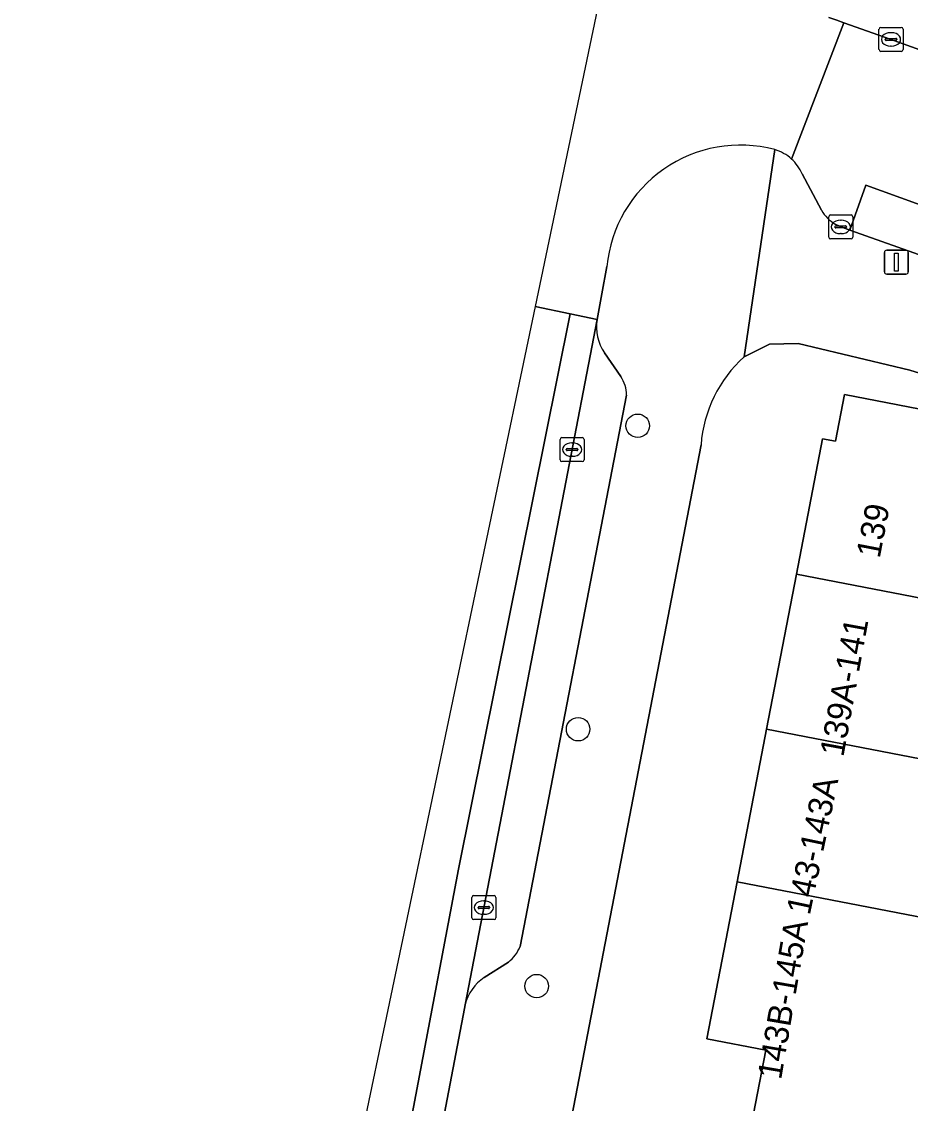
# Model space of a CAD drawing. Extents: x 159817 to 160765, y 380688 to 381638.
# Drawn here: x 159990.41 to 160027.41, y 381065.22 to 381110.28 of the extents above; entities that cross this region are included whole.
import ezdxf

# ---------------------------------------------------------------- set-up
doc = ezdxf.new("R2010")
doc.units = 0
for name, color, linetype in [('IMGEO_Boom', 7, 'Continuous'), ('IMGEO_Erf', 7, 'Continuous'), ('IMGEO_Kolk', 7, 'Continuous'), ('IMGEO_Lichtmast', 7, 'Continuous'), ('IMGEO_Pand', 7, 'Continuous'), ('IMGEO_Pand_nummerreeks', 7, 'Continuous'), ('IMGEO_Parkeervlak_open', 7, 'Continuous'), ('IMGEO_Rijbaan_lokaal_gesloten', 7, 'Continuous'), ('IMGEO_Rijbaan_lokaal_open', 7, 'Continuous'), ('IMGEO_Voetpad_open', 7, 'Continuous')]:
    doc.layers.add(name, color=color, linetype=linetype)

msp = doc.modelspace()

# ---------------------------------------------------------------- linework, layer by layer
at = {"layer": 'IMGEO_Boom'}
for centre in [(160016.059, 381093.448), (160013.577, 381080.809), (160011.851, 381070.108)]:
    msp.add_circle(centre, 0.489, dxfattribs=at)
at = {"layer": 'IMGEO_Erf'}
for points in [[(160050.272, 381088.672), (160027.383, 381095.765), (160022.739, 381096.87), (160021.552, 381096.842), (160020.487, 381096.319)], [(160018.697, 381092.654), (160013.182, 381063.968), (160020.449, 381062.565), (160021.389, 381067.434), (160018.934, 381067.908), (160020.197, 381074.451), (160021.425, 381080.816), (160022.671, 381087.27), (160023.759, 381092.908), (160024.29, 381092.806), (160024.664, 381094.748), (160029.108, 381093.89), (160028.732, 381091.944), (160032.76, 381091.167), (160032.532, 381089.988), (160036.377, 381088.829), (160049.13, 381084.986), (160050.272, 381088.672)]]:
    msp.add_lwpolyline(points, dxfattribs=at)
msp.add_arc((160024.132, 381092.269), 5.449, 131.9899, 175.9479, dxfattribs=at)
at = {"layer": 'IMGEO_Kolk'}
for p, q in [((160026.105, 381109.115), (160026.105, 381109.967)), ((160026.18, 381110.041), (160027.032, 381110.041)), ((160026.593, 381109.821), (160026.618, 381109.821)), ((160027.106, 381109.967), (160027.106, 381109.115)), ((160026.364, 381109.535), (160026.364, 381109.547)), ((160026.802, 381109.498), (160026.404, 381109.498)), ((160026.407, 381109.584), (160026.805, 381109.584)), ((160026.848, 381109.547), (160026.848, 381109.535)), ((160027.032, 381109.041), (160026.18, 381109.041)), ((160026.616, 381109.261), (160026.591, 381109.261)), ((160024.013, 381101.304), (160024.013, 381102.156)), ((160024.088, 381102.23), (160024.94, 381102.23)), ((160025.014, 381102.156), (160025.014, 381101.304)), ((160024.272, 381101.724), (160024.272, 381101.736)), ((160024.315, 381101.773), (160024.713, 381101.773)), ((160024.501, 381102.01), (160024.526, 381102.01)), ((160024.756, 381101.736), (160024.756, 381101.724)), ((160024.71, 381101.687), (160024.312, 381101.687)), ((160024.524, 381101.45), (160024.499, 381101.45)), ((160024.94, 381101.23), (160024.088, 381101.23)), ((160012.826, 381092.029), (160012.826, 381092.881)), ((160012.901, 381092.955), (160013.753, 381092.955)), ((160013.314, 381092.735), (160013.339, 381092.735)), ((160013.827, 381092.881), (160013.827, 381092.029)), ((160013.085, 381092.449), (160013.085, 381092.461)), ((160013.523, 381092.412), (160013.125, 381092.412)), ((160013.128, 381092.498), (160013.526, 381092.498)), ((160013.569, 381092.461), (160013.569, 381092.449)), ((160013.753, 381091.955), (160012.901, 381091.955)), ((160013.337, 381092.175), (160013.312, 381092.175)), ((160009.152, 381072.954), (160009.152, 381073.806)), ((160009.227, 381073.88), (160010.079, 381073.88)), ((160010.153, 381073.806), (160010.153, 381072.954)), ((160009.411, 381073.374), (160009.411, 381073.386)), ((160009.849, 381073.337), (160009.451, 381073.337)), ((160009.454, 381073.423), (160009.852, 381073.423)), ((160009.64, 381073.66), (160009.665, 381073.66)), ((160009.895, 381073.386), (160009.895, 381073.374)), ((160010.079, 381072.88), (160009.227, 381072.88)), ((160009.663, 381073.1), (160009.638, 381073.1))]:
    msp.add_line(p, q, dxfattribs=at)
for points in [[(160026.105, 381109.115), (160026.105, 381109.967)], [(160026.18, 381110.041), (160027.032, 381110.041)], [(160027.106, 381109.967), (160027.106, 381109.115)], [(160027.032, 381109.041), (160026.18, 381109.041)], [(160024.013, 381101.304), (160024.013, 381102.156)], [(160024.088, 381102.23), (160024.94, 381102.23)], [(160025.014, 381102.156), (160025.014, 381101.304)], [(160024.94, 381101.23), (160024.088, 381101.23)], [(160012.826, 381092.029), (160012.826, 381092.881)], [(160012.901, 381092.955), (160013.753, 381092.955)], [(160013.827, 381092.881), (160013.827, 381092.029)], [(160013.753, 381091.955), (160012.901, 381091.955)], [(160009.152, 381072.954), (160009.152, 381073.806)], [(160009.227, 381073.88), (160010.079, 381073.88)], [(160010.153, 381073.806), (160010.153, 381072.954)], [(160010.079, 381072.88), (160009.227, 381072.88)]]:
    msp.add_lwpolyline(points, dxfattribs=at)
for centre, radius, start, end in [((160026.182, 381109.965), 0.0765, 91.552, 178.448), ((160026.182, 381109.965), 0.0765, 91.552, 178.448), ((160027.03, 381109.965), 0.0765, 1.552, 88.448), ((160027.03, 381109.965), 0.0765, 1.552, 88.448), ((160026.404, 381109.544), 0.0403, 85.8775, 175.7526), ((160026.401, 381109.534), 0.0366, 178.938, 274.7102), ((160026.805, 381109.541), 0.043, 264.8664, 352.4533), ((160026.809, 381109.546), 0.0386, 1.7309, 96.639), ((160026.182, 381109.117), 0.0765, 181.552, 268.448), ((160026.182, 381109.117), 0.0765, 181.552, 268.448), ((160027.03, 381109.117), 0.0765, 271.552, 358.448), ((160027.03, 381109.117), 0.0765, 271.552, 358.448), ((160024.09, 381102.154), 0.0765, 91.552, 178.448), ((160024.09, 381102.154), 0.0765, 91.552, 178.448), ((160024.938, 381102.154), 0.0765, 1.552, 88.448), ((160024.938, 381102.154), 0.0765, 1.552, 88.448), ((160024.312, 381101.733), 0.0403, 85.8775, 175.7526), ((160024.309, 381101.723), 0.0366, 178.938, 274.7102), ((160024.713, 381101.73), 0.043, 264.8664, 352.4533), ((160024.717, 381101.735), 0.0386, 1.7309, 96.639), ((160024.09, 381101.306), 0.0765, 181.552, 268.448), ((160024.09, 381101.306), 0.0765, 181.552, 268.448), ((160024.938, 381101.306), 0.0765, 271.552, 358.448), ((160024.938, 381101.306), 0.0765, 271.552, 358.448), ((160012.903, 381092.879), 0.0765, 91.552, 178.448), ((160012.903, 381092.879), 0.0765, 91.552, 178.448), ((160013.751, 381092.879), 0.0765, 1.552, 88.448), ((160013.751, 381092.879), 0.0765, 1.552, 88.448), ((160013.125, 381092.458), 0.0403, 85.8775, 175.7526), ((160013.122, 381092.448), 0.0366, 178.938, 274.7102), ((160013.526, 381092.455), 0.043, 264.8664, 352.4533), ((160013.53, 381092.46), 0.0386, 1.7309, 96.639), ((160012.903, 381092.031), 0.0765, 181.552, 268.448), ((160012.903, 381092.031), 0.0765, 181.552, 268.448), ((160013.751, 381092.031), 0.0765, 271.552, 358.448), ((160013.751, 381092.031), 0.0765, 271.552, 358.448), ((160009.229, 381073.804), 0.0765, 91.552, 178.448), ((160009.229, 381073.804), 0.0765, 91.552, 178.448), ((160010.077, 381073.804), 0.0765, 1.552, 88.448), ((160010.077, 381073.804), 0.0765, 1.552, 88.448), ((160009.451, 381073.383), 0.0403, 85.8775, 175.7526), ((160009.448, 381073.373), 0.0366, 178.938, 274.7102), ((160009.852, 381073.38), 0.043, 264.8664, 352.4533), ((160009.856, 381073.385), 0.0386, 1.7309, 96.639), ((160009.229, 381072.956), 0.0765, 181.552, 268.448), ((160009.229, 381072.956), 0.0765, 181.552, 268.448), ((160010.077, 381072.956), 0.0765, 271.552, 358.448), ((160010.077, 381072.956), 0.0765, 271.552, 358.448)]:
    msp.add_arc(centre, radius, start, end, dxfattribs=at)
for centre, major_axis, ratio, start_param, end_param in [((160026.592, 381109.541), (-0.387, 0.002), 0.722429, 4.712389, 7.853982), ((160026.617, 381109.541), (-0.39, 0.002), 0.717154, 1.570796, 4.712389), ((160024.5, 381101.73), (-0.387, 0.002), 0.722429, 4.712389, 7.853982), ((160024.525, 381101.73), (-0.39, 0.002), 0.717154, 1.570796, 4.712389), ((160013.313, 381092.455), (-0.387, 0.002), 0.722429, 4.712389, 7.853982), ((160013.338, 381092.455), (-0.39, 0.002), 0.717154, 1.570796, 4.712389), ((160009.639, 381073.38), (-0.387, 0.002), 0.722429, 4.712389, 7.853982), ((160009.664, 381073.38), (-0.39, 0.002), 0.717154, 1.570796, 4.712389)]:
    msp.add_ellipse(centre, major_axis=major_axis, ratio=ratio, start_param=start_param, end_param=end_param, dxfattribs=at)
at = {"layer": 'IMGEO_Lichtmast'}
for p, q in [((160026.333, 381099.862), (160026.333, 381100.662)), ((160026.333, 381100.662), (160026.333, 381099.862)), ((160026.433, 381100.762), (160027.223, 381100.762)), ((160027.223, 381100.762), (160026.433, 381100.762)), ((160027.323, 381100.662), (160027.323, 381099.862)), ((160027.323, 381099.862), (160027.323, 381100.662)), ((160027.223, 381099.762), (160026.433, 381099.762)), ((160026.433, 381099.762), (160027.223, 381099.762))]:
    msp.add_line(p, q, dxfattribs=at)
msp.add_lwpolyline([(160026.753, 381100.637), (160026.903, 381100.637), (160026.903, 381099.887), (160026.753, 381099.887), (160026.753, 381100.637)], dxfattribs=at)
for centre, start, end in [((160026.433, 381100.662), 90, 180), ((160026.433, 381100.662), 90, 180), ((160027.223, 381100.662), 0, 90), ((160027.223, 381100.662), 360, 90), ((160026.433, 381099.862), 180, 270), ((160026.433, 381099.862), 180, 270), ((160027.223, 381099.862), 270, 0), ((160027.223, 381099.862), 270, 0)]:
    msp.add_arc(centre, 0.1, start, end, dxfattribs=at)
at = {"layer": 'IMGEO_Pand'}
for points in [[(160035.179, 381084.856), (160036.377, 381088.829), (160032.532, 381089.988), (160032.76, 381091.167), (160028.732, 381091.944), (160029.108, 381093.89), (160024.664, 381094.748), (160024.29, 381092.806), (160023.759, 381092.908), (160022.671, 381087.27)], [(160021.425, 381080.816), (160034.222, 381078.346), (160034.983, 381082.289), (160034.453, 381082.449), (160035.179, 381084.856), (160022.671, 381087.27)], [(160021.425, 381080.816), (160020.197, 381074.451), (160038.181, 381070.98), (160039.211, 381077.288), (160034.222, 381078.346)], [(160038.181, 381070.98), (160020.197, 381074.451), (160018.934, 381067.908), (160021.389, 381067.434), (160020.449, 381062.565), (160025.359, 381061.617), (160037.632, 381059.249), (160037.702, 381059.613), (160038.584, 381064.177), (160038.637, 381064.454), (160037.162, 381064.74)]]:
    msp.add_lwpolyline(points, close=True, dxfattribs=at)
at = {"layer": 'IMGEO_Parkeervlak_open'}
msp.add_lwpolyline([(160024.886, 381101.599), (160029.549, 381099.944), (160043.748, 381094.789), (160047.251, 381093.529), (160047.916, 381095.371), (160025.551, 381103.473)], close=True, dxfattribs=at)
for points in [[(160014.37, 381097.873), (160008.872, 381069.326)], [(160015.36, 381095.497), (160014.672, 381096.487)], [(160011.162, 381071.761), (160015.595, 381094.725)], [(160009.67, 381070.467), (160010.674, 381071.111)]]:
    msp.add_lwpolyline(points, dxfattribs=at)
for centre, radius, start, end in [((160016.26, 381097.559), 1.916, 170.5634, 214.021), ((160014.141, 381094.704), 1.454, 0.8241, 33.0369), ((160009.739, 381072.321), 1.529, 307.6874, 338.5165), ((160010.708, 381068.892), 1.886, 123.3741, 166.6891)]:
    msp.add_arc(centre, radius, start, end, dxfattribs=at)
at = {"layer": 'IMGEO_Rijbaan_lokaal_gesloten'}
for points in [[(159996.492, 381024.81), (159998.992, 381024.304), (160001.883, 381039.437), (160008.595, 381074.982), (160013.251, 381098.111), (160011.786, 381098.422), (159998.48, 381034.852)], [(160007.891, 381064.168), (160008.842, 381069.172), (160008.872, 381069.326), (160014.37, 381097.873), (160013.251, 381098.111), (160008.595, 381074.982), (160001.883, 381039.437), (159998.992, 381024.304), (160000.051, 381024.089), (160000.137, 381024.388)]]:
    msp.add_lwpolyline(points, close=True, dxfattribs=at)
at = {"layer": 'IMGEO_Rijbaan_lokaal_open'}
for points in [[(160019.877, 381118.182), (160020.066, 381119.039), (160019.037, 381119.34), (160017.102, 381119.905), (160017.102, 381119.905), (160015.579, 381116.542), (160011.786, 381098.422)], [(160022.465, 381104.557), (160024.642, 381110.234), (160024.343, 381110.34), (160024.015, 381110.456)], [(160046.79, 381102.26), (160038.233, 381105.355), (160026.573, 381109.552), (160024.642, 381110.234), (160022.465, 381104.557)], [(160022.905, 381103.939), (160023.713, 381102.422)], [(160024.277, 381101.844), (160024.486, 381101.741), (160024.886, 381101.599), (160025.551, 381103.473), (160047.916, 381095.371), (160049.988, 381101.106), (160046.79, 381102.26)], [(160011.786, 381098.422), (160013.251, 381098.111), (160014.37, 381097.873), (160014.565, 381098.948), (160014.775, 381100.079)]]:
    msp.add_lwpolyline(points, dxfattribs=at)
for centre, radius, start, end in [((160020.333, 381099.555), 5.583, 75.1582, 174.6099), ((160021.24, 381103.197), 1.83, 47.9894, 73.4036), ((160021.265, 381103.237), 1.784, 23.1707, 47.7291), ((160025.264, 381103.371), 1.819, 211.47, 237.1252)]:
    msp.add_arc(centre, radius, start, end, dxfattribs=at)
at = {"layer": 'IMGEO_Voetpad_open'}
for points in [[(160024.015, 381110.456), (160024.343, 381110.34), (160024.642, 381110.234), (160026.573, 381109.552), (160038.233, 381105.355), (160046.79, 381102.26), (160049.988, 381101.106), (160052.584, 381100.169), (160064.212, 381095.974)], [(160020.487, 381096.319), (160021.763, 381104.951)], [(160021.763, 381104.951), (160020.487, 381096.319), (160021.552, 381096.842), (160022.739, 381096.87), (160027.383, 381095.765), (160050.272, 381088.672), (160051.813, 381088.194), (160072.621, 381081.745), (160077.116, 381080.392)], [(160023.713, 381102.422), (160022.905, 381103.939)], [(160049.848, 381092.595), (160047.251, 381093.529), (160043.748, 381094.789), (160029.549, 381099.944), (160024.886, 381101.599), (160024.486, 381101.741), (160024.277, 381101.844)], [(160014.775, 381100.079), (160014.565, 381098.948), (160014.37, 381097.873)], [(160014.672, 381096.487), (160015.36, 381095.497)], [(160015.595, 381094.725), (160011.162, 381071.761)], [(159990.408, 380945.519), (160000, 380995.407), (160000.883, 381000), (160001.431, 381002.849), (160001.992, 381005.764), (160001.994, 381005.776), (160012.912, 381062.566), (160013.182, 381063.968), (160018.697, 381092.654)], [(160010.674, 381071.111), (160009.67, 381070.467)], [(160008.872, 381069.326), (160008.842, 381069.172), (160007.891, 381064.168)]]:
    msp.add_lwpolyline(points, dxfattribs=at)
for centre, radius, start, end in [((160020.333, 381099.555), 5.583, 75.1582, 174.6099), ((160021.24, 381103.197), 1.83, 47.9894, 73.4036), ((160021.265, 381103.237), 1.784, 23.1707, 47.7291), ((160025.264, 381103.371), 1.819, 211.47, 237.1252), ((160016.26, 381097.559), 1.916, 170.5634, 214.021), ((160024.132, 381092.269), 5.449, 131.9899, 175.9479), ((160014.141, 381094.704), 1.454, 0.8241, 33.0369), ((160009.739, 381072.321), 1.529, 307.6874, 338.5165), ((160010.708, 381068.892), 1.886, 123.3741, 166.6891)]:
    msp.add_arc(centre, radius, start, end, dxfattribs=at)

# ---------------------------------------------------------------- texts
at = {"layer": 'IMGEO_Pand_nummerreeks'}
for s, rotation, p in [('139', 79.0762, (160026.133, 381087.896)), ('139A-141', 79.5767, (160024.619, 381079.625)), ('143-143A', 78.0814, (160023.221, 381073.031)), ('143B-145A', 80.2599, (160022.027, 381066.181))]:
    msp.add_text(s, height=1, rotation=rotation, dxfattribs=at).set_placement(p)

doc.saveas('drawing.dxf')
